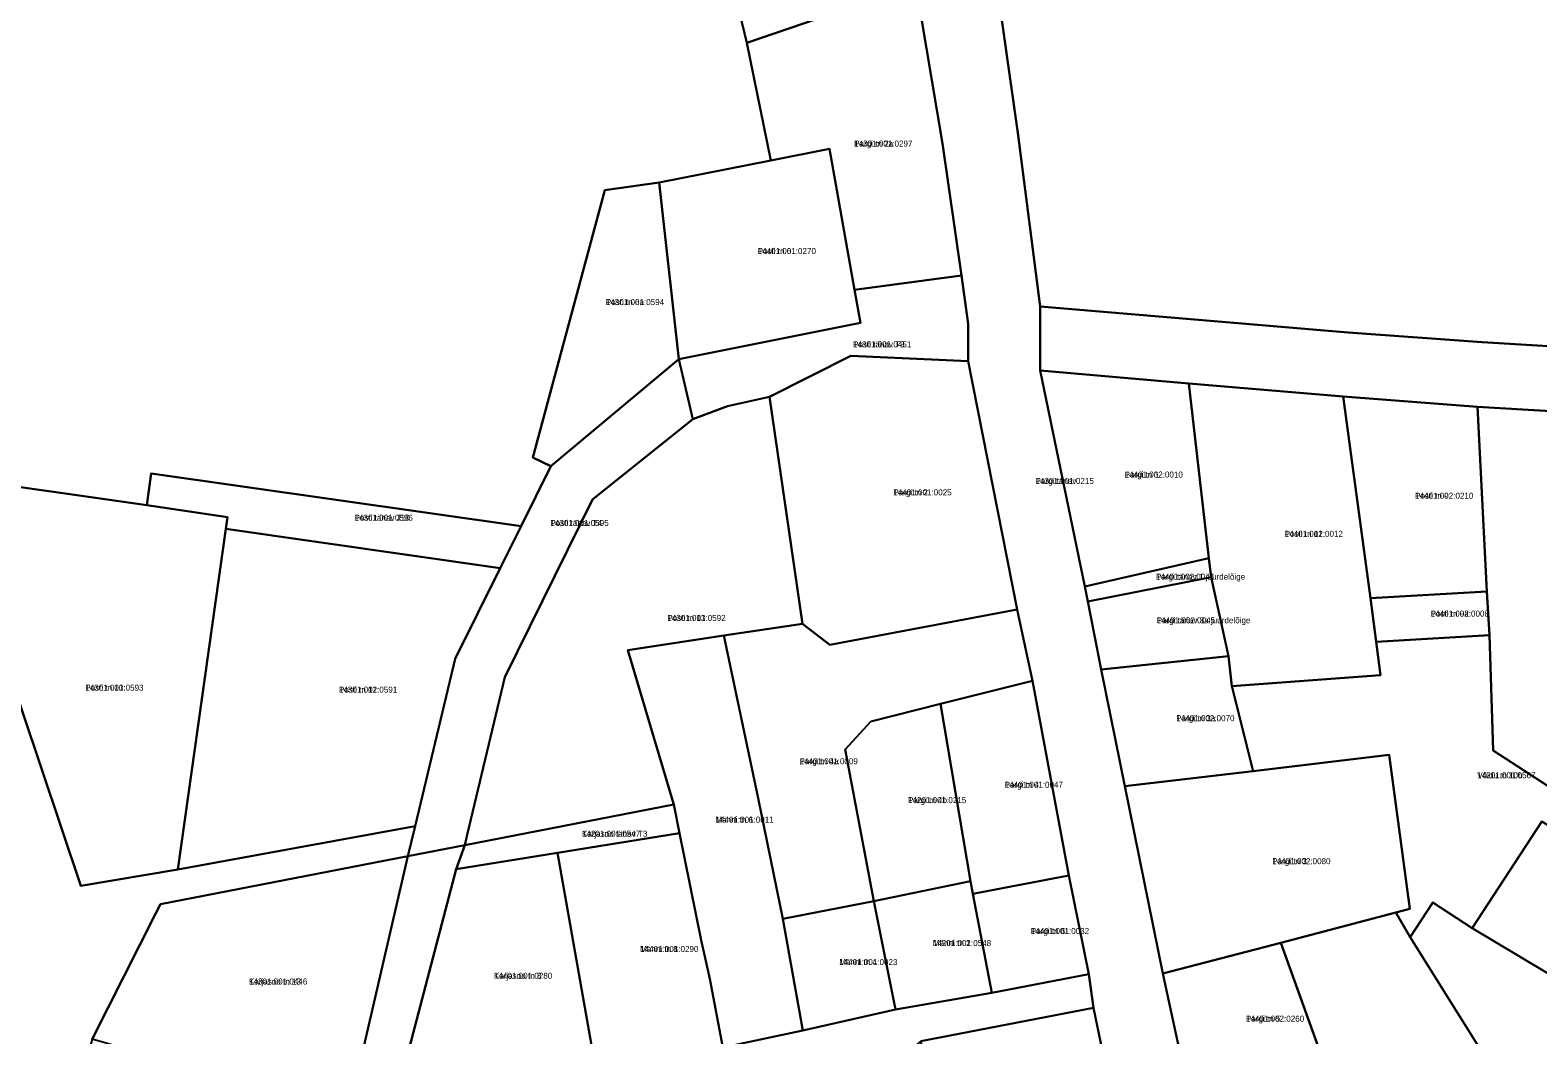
# Model space of a CAD drawing. Extents: x 640657 to 665127, y 6395726 to 6426831.
# Drawn here: x 649552.6 to 649927.6, y 6412380.5 to 6412630.2 of the extents above; entities that cross this region are included whole.
import ezdxf

# ---------------------------------------------------------------- set-up
doc = ezdxf.new("R2010")
doc.units = 0
for name, color, linetype in [('L_AADRESS', 7, 'Continuous'), ('PIIR', 7, 'Continuous'), ('TUNNUS', 7, 'Continuous')]:
    doc.layers.add(name, color=color, linetype=linetype)

msp = doc.modelspace()

# ---------------------------------------------------------------- linework, layer by layer
at = {"layer": 'PIIR'}
for points in [[(649711.66, 6412706.61), (649752.16, 6412713.93), (649758.11, 6412711.02), (649772.83, 6412641.44), (649730.85, 6412627.05), (649721.82, 6412664.46)], [(649784.19, 6412569.18), (649757.64, 6412565.61), (649751.39, 6412600.65), (649736.82, 6412597.75), (649730.85, 6412627.05), (649772.83, 6412641.44), (649779.5, 6412602)], [(649709.02, 6412592.28), (649736.82, 6412597.75), (649751.39, 6412600.65), (649757.64, 6412565.61), (649759.08, 6412557.47), (649713.89, 6412548.39)], [(649695.48, 6412590.41), (649709.02, 6412592.28), (649713.89, 6412548.39), (649682.12, 6412521.81), (649677.65, 6412523.96)], [(649713.89, 6412548.39), (649759.08, 6412557.47), (649757.64, 6412565.61), (649784.19, 6412569.18), (649785.9, 6412557.2), (649785.9, 6412547.9), (649756.7, 6412549.2), (649736.51, 6412539.03), (649726.01, 6412536.74), (649717.4, 6412533.5)], [(649803.8, 6412545.57), (649803.8, 6412561.5), (649842.2, 6412558.3), (649880.4, 6412555), (649913.7, 6412552.6), (649950.8, 6412550.4), (649980.06, 6412552.77), (649998.34, 6412540.87), (650017.02, 6412528.86), (650039.58, 6412514.37), (650033.45, 6412504.9), (649996.8, 6412527.89), (649991.28, 6412529.73), (649949, 6412534.42), (649912.56, 6412536.54), (649879.16, 6412539.16), (649840.77, 6412542.38)], [(649682.12, 6412521.81), (649713.89, 6412548.39), (649717.4, 6412533.5), (649692.42, 6412513.52), (649670.67, 6412469.37), (649661.29, 6412430.18), (649660.68, 6412427.63), (649646.56, 6412424.89), (649648.34, 6412432.29), (649658.34, 6412473.88), (649669.49, 6412496.48), (649674.69, 6412506.86)], [(649798.04, 6412486.14), (649751.48, 6412477.38), (649744.68, 6412482.58), (649736.51, 6412539.03), (649756.7, 6412549.2), (649785.9, 6412547.9)], [(649840.77, 6412542.38), (649845.74, 6412498.97), (649814.87, 6412491.92), (649803.8, 6412545.57)], [(649840.77, 6412542.38), (649879.16, 6412539.16), (649885.94, 6412489), (649888.39, 6412469.87), (649851.44, 6412467.1), (649850.66, 6412474.57), (649846.28, 6412494.22), (649845.74, 6412498.97)], [(649726.01, 6412536.74), (649736.51, 6412539.03), (649744.68, 6412482.58), (649725.11, 6412479.68), (649701.28, 6412476.03), (649712.08, 6412439.62), (649712.65, 6412437.7), (649660.68, 6412427.63), (649661.29, 6412430.18), (649670.67, 6412469.37), (649692.42, 6412513.52), (649717.4, 6412533.5)], [(649912.56, 6412536.54), (649914.89, 6412490.68), (649885.94, 6412489), (649879.16, 6412539.16)], [(649912.56, 6412536.54), (649949, 6412534.42), (649940.97, 6412435.19), (649916.45, 6412451.11), (649915.5, 6412479.78), (649914.89, 6412490.68)], [(649582.66, 6412520.01), (649674.69, 6412506.86), (649669.49, 6412496.48), (649601.27, 6412506.2), (649601.67, 6412509.16), (649581.58, 6412512.13)], [(649565.2, 6412417.51), (649530.93, 6412519.33), (649581.58, 6412512.13), (649601.67, 6412509.16), (649601.27, 6412506.2), (649589.31, 6412421.53)], [(649589.31, 6412421.53), (649601.27, 6412506.2), (649669.49, 6412496.48), (649658.34, 6412473.88), (649648.34, 6412432.29)], [(649814.87, 6412491.92), (649845.74, 6412498.97), (649846.28, 6412494.22), (649815.62, 6412488.19)], [(649815.62, 6412488.19), (649846.28, 6412494.22), (649850.66, 6412474.57), (649818.99, 6412471.29)], [(649885.94, 6412489), (649914.89, 6412490.68), (649915.5, 6412479.78), (649887.36, 6412478.15)], [(649725.11, 6412479.68), (649744.68, 6412482.58), (649751.48, 6412477.38), (649798.04, 6412486.14), (649798.61, 6412483.47), (649801.85, 6412468.42), (649779, 6412462.69), (649761.7, 6412458.36), (649755.33, 6412451.36), (649762.38, 6412413.67), (649739.77, 6412409.28), (649733.64, 6412439.3)], [(649744.78, 6412381.55), (649724.89, 6412377.34), (649721.61, 6412394.38), (649719.48, 6412403.99), (649714.06, 6412430.6), (649712.65, 6412437.7), (649712.08, 6412439.62), (649701.28, 6412476.03), (649725.11, 6412479.68), (649733.64, 6412439.3), (649739.77, 6412409.28)], [(649888.39, 6412469.87), (649887.36, 6412478.15), (649915.5, 6412479.78), (649916.45, 6412451.11), (649940.97, 6412435.19), (649940.46, 6412428.95), (649947.82, 6412430.62), (649961.58, 6412421.62), (649973.55, 6412413.79), (649970.1, 6412408.7), (649928.57, 6412433.48), (649911.24, 6412406.94), (649901.45, 6412413.33), (649895.82, 6412404.71), (649892.26, 6412410.82), (649895.71, 6412411.75), (649890.54, 6412450.01), (649856.78, 6412446.02), (649851.44, 6412467.1)], [(649850.66, 6412474.57), (649851.44, 6412467.1), (649856.78, 6412446.02), (649824.87, 6412442.25), (649818.99, 6412471.29)], [(649779, 6412462.69), (649801.85, 6412468.42), (649810.91, 6412420.08), (649787.06, 6412415.53), (649786.5, 6412418.61)], [(649761.7, 6412458.36), (649779, 6412462.69), (649786.5, 6412418.61), (649762.38, 6412413.67), (649755.33, 6412451.36)], [(649834.26, 6412395.72), (649824.87, 6412442.25), (649856.78, 6412446.02), (649890.54, 6412450.01), (649895.71, 6412411.75), (649892.26, 6412410.82), (649863.6, 6412403.34)], [(649683.72, 6412425.67), (649658.51, 6412421.66), (649660.68, 6412427.63), (649712.65, 6412437.7), (649714.06, 6412430.6)], [(649683.72, 6412425.67), (649714.06, 6412430.6), (649719.48, 6412403.99), (649721.61, 6412394.38), (649724.89, 6412377.34), (649693.47, 6412370.82)], [(649952.6, 6412382.3), (649911.24, 6412406.94), (649928.57, 6412433.48), (649970.1, 6412408.7)], [(649599.46, 6412190.55), (649581.09, 6412182.7), (649591.31, 6412214.32), (649592.88, 6412218.54), (649595.75, 6412226.18), (649609.52, 6412272.16), (649620.19, 6412314.5), (649631.74, 6412361.02), (649646.56, 6412424.89), (649660.68, 6412427.63), (649658.51, 6412421.66), (649642.44, 6412360.34), (649640.7, 6412346.54), (649626.17, 6412285.93), (649621.96, 6412267), (649609.71, 6412230.22), (649600.49, 6412201.9), (649598.79, 6412196.69)], [(649568.03, 6412379.35), (649583.88, 6412410.73), (649585.01, 6412412.96), (649646.56, 6412424.89), (649631.74, 6412361.02)], [(649658.51, 6412421.66), (649683.72, 6412425.67), (649693.47, 6412370.82), (649642.44, 6412360.34)], [(649810.91, 6412420.08), (649815.85, 6412395.56), (649791.8, 6412390.86), (649787.06, 6412415.53)], [(649762.38, 6412413.67), (649786.5, 6412418.61), (649787.06, 6412415.53), (649791.8, 6412390.86), (649767.83, 6412386.75)], [(649744.78, 6412381.55), (649739.77, 6412409.28), (649762.38, 6412413.67), (649767.83, 6412386.75)], [(649901.45, 6412413.33), (649911.24, 6412406.94), (649952.6, 6412382.3), (649930.7, 6412349), (649895.82, 6412404.71)], [(649930.7, 6412349), (649917, 6412327.3), (649914.43, 6412323.17), (649894.69, 6412315.18), (649883.22, 6412348.91), (649875.65, 6412369.9), (649863.6, 6412403.34), (649892.26, 6412410.82), (649895.82, 6412404.71)], [(649834.26, 6412395.72), (649863.6, 6412403.34), (649875.65, 6412369.9), (649841.15, 6412363.99)], [(649642.44, 6412360.34), (649693.47, 6412370.82), (649724.89, 6412377.34), (649744.78, 6412381.55), (649767.83, 6412386.75), (649791.8, 6412390.86), (649815.85, 6412395.56), (649817.07, 6412387.2), (649774.12, 6412378.85), (649769.02, 6412374.6), (649731.18, 6412366.4), (649707.22, 6412361.37), (649682.96, 6412355.22), (649657.78, 6412349.92), (649640.7, 6412346.54)], [(649774.12, 6412378.85), (649817.07, 6412387.2), (649824.2, 6412352.76), (649783.35, 6412345.04)]]:
    msp.add_lwpolyline(points, close=True, dxfattribs=at)
for points in [[(649721.82, 6412664.46), (649730.85, 6412627.05), (649736.82, 6412597.75), (649709.02, 6412592.28), (649695.48, 6412590.41), (649677.65, 6412523.96), (649682.12, 6412521.81), (649674.69, 6412506.86), (649582.66, 6412520.01), (649581.58, 6412512.13), (649530.93, 6412519.33), (649565.2, 6412417.51), (649589.31, 6412421.53), (649648.34, 6412432.29), (649646.56, 6412424.89), (649585.01, 6412412.96), (649583.88, 6412410.73), (649568.03, 6412379.35), (649559.94, 6412349.89), (649537.28, 6412345.21)], [(650021.1, 6412653.3), (650007.16, 6412599.18), (649982.2, 6412556.55), (649980.06, 6412552.77), (649950.8, 6412550.4), (649913.7, 6412552.6), (649880.4, 6412555), (649842.2, 6412558.3), (649803.8, 6412561.5), (649798.2, 6412604.7), (649792.4, 6412645.6)], [(649792.4, 6412645.6), (649798.2, 6412604.7), (649803.8, 6412561.5), (649803.8, 6412545.57), (649814.87, 6412491.92), (649815.62, 6412488.19), (649818.99, 6412471.29), (649824.87, 6412442.25), (649834.26, 6412395.72), (649841.16, 6412363.98)], [(649824.2, 6412352.76), (649817.07, 6412387.2), (649815.85, 6412395.56), (649810.91, 6412420.08), (649801.85, 6412468.42), (649798.61, 6412483.47), (649798.04, 6412486.14), (649785.9, 6412547.9), (649785.9, 6412557.2), (649784.19, 6412569.18), (649779.5, 6412602), (649772.83, 6412641.44)]]:
    msp.add_lwpolyline(points, dxfattribs=at)

# ---------------------------------------------------------------- texts
at = {"layer": 'L_AADRESS'}
for s, p in [('Pargi tn 2a', (649757.52, 6412601.24)), ('Posti tn 6', (649733.52, 6412574.52)), ('Posti tn 6a', (649695.77, 6412561.84)), ('Posti tänav T3', (649757.24, 6412551.34)), ('Pargi tn 1', (649824.77, 6412518.97)), ('Pargi tn 2', (649767.27, 6412514.54)), ('Pargi tänav', (649802.63, 6412517.39)), ('Posti tn 9', (649897.02, 6412513.7)), ('Posti tänav J10', (649633.27, 6412508.25)), ('Posti tänav T4', (649681.98, 6412506.93)), ('Posti tn 11', (649864.58, 6412504.23)), ('Pargi tänav 1 juurdelõige', (649832.58, 6412493.58)), ('Posti tn 13', (649711.06, 6412483.33)), ('Pargi tänav 3a juurdelõige', (649832.77, 6412482.75)), ('Posti tn 9a', (649900.89, 6412484.41)), ('Posti tn 10', (649566.3, 6412466)), ('Posti tn 12', (649629.4, 6412465.51)), ('Pargi tn 3a', (649837.62, 6412458.41)), ('Pargi tn 4a', (649743.94, 6412447.71)), ('Võidu tn 10b', (649912.49, 6412444.23)), ('Pargi tn 4', (649794.95, 6412441.86)), ('Pargi tn 4b', (649770.91, 6412438.04)), ('Männi tn 6', (649723.03, 6412433.18)), ('Karjasoo tänav T3', (649689.83, 6412429.68)), ('Pargi tn 3', (649861.5, 6412422.87)), ('Männi tn 2', (649777.09, 6412402.51)), ('Pargi tn 6', (649801.46, 6412405.51)), ('Männi tn 8', (649704.3, 6412401.04)), ('Männi tn 4', (649753.8, 6412397.79)), ('Karjasoo tn 13', (649607.03, 6412392.96)), ('Karjasoo tn 8', (649667.95, 6412394.37)), ('Pargi tn 5', (649854.95, 6412383.72))]:
    msp.add_text(s, height=1.5, dxfattribs=at).set_placement(p)
at = {"layer": 'TUNNUS'}
for s, p in [('14301:001:0297', (649757.52, 6412601.24)), ('14401:001:0270', (649733.52, 6412574.52)), ('14301:001:0594', (649695.77, 6412561.84)), ('14301:001:0451', (649757.24, 6412551.34)), ('14401:002:0010', (649824.77, 6412518.97)), ('14301:001:0215', (649802.63, 6412517.39)), ('14401:001:0025', (649767.27, 6412514.54)), ('14401:002:0210', (649897.02, 6412513.7)), ('14301:001:0596', (649633.27, 6412508.25)), ('14301:001:0595', (649681.98, 6412506.93)), ('14401:002:0012', (649864.58, 6412504.23)), ('14401:002:0044', (649832.58, 6412493.58)), ('14301:001:0592', (649711.06, 6412483.33)), ('14401:002:0045', (649832.77, 6412482.75)), ('14401:002:0008', (649900.89, 6412484.41)), ('14301:001:0593', (649566.3, 6412466)), ('14301:001:0591', (649629.4, 6412465.51)), ('14401:002:0070', (649837.62, 6412458.41)), ('14401:001:0009', (649743.94, 6412447.71)), ('14201:001:0567', (649912.49, 6412444.23)), ('14401:001:0047', (649794.95, 6412441.86)), ('14201:001:0215', (649770.91, 6412438.04)), ('14401:001:0011', (649723.03, 6412433.18)), ('14201:001:0547', (649689.83, 6412429.68)), ('14401:002:0080', (649861.5, 6412422.87)), ('14201:001:0548', (649777.09, 6412402.51)), ('14401:001:0032', (649801.46, 6412405.51)), ('14401:001:0290', (649704.3, 6412401.04)), ('14401:001:0023', (649753.8, 6412397.79)), ('14301:001:0446', (649607.03, 6412392.96)), ('14401:001:0280', (649667.95, 6412394.37)), ('14401:002:0260', (649854.95, 6412383.72))]:
    msp.add_text(s, height=1.5, dxfattribs=at).set_placement(p)

doc.saveas('drawing.dxf')
